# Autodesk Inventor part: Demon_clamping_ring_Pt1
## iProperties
Shininess: 64.0
Length Units: 11269
Angle Units: 11279
Time Units: 11290
Mass Units: 11283
Length Display Precision: 3
Angle Display Precision: 2
Compacted: True
Part Number: Demon_clamping_ring_Pt1
Document SubType Name: Modeling
Created: 2005-04
Designer: John Blackburn
Manufacturer: Standard
Standards Organization: Custom
Material: Aluminum-6061
Density: 0.0
Volumn: 0.0
Area: 0.0
PropertySet Name: Model Information
Control State: 0
Master: False
Checked Out: False
Author: John Blackburn
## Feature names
1. Extrusion1
2. Extrusion3
